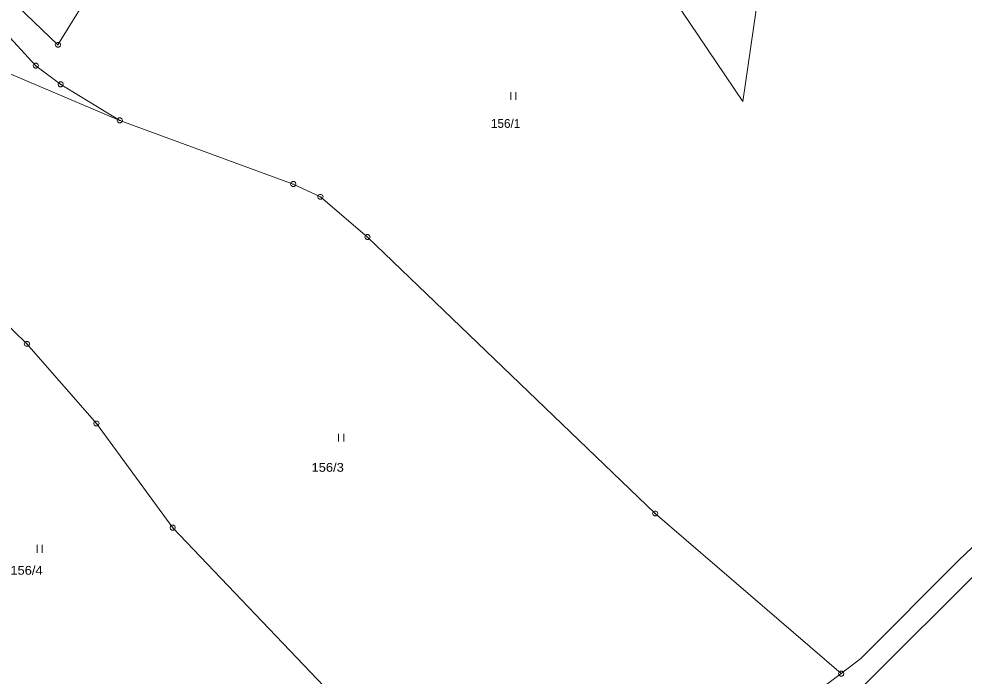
# Model space of a CAD drawing. Extents: x -687390 to -684106, y -954833 to -951648.
# Drawn here: x -686858.8 to -686675.9, y -952746.6 to -952619.4 of the extents above; entities that cross this region are included whole.
import ezdxf

# ---------------------------------------------------------------- set-up
doc = ezdxf.new("R2010")
doc.units = 0
doc.header["$LTSCALE"] = 0.68
for name, color, linetype, lineweight in [('1', 7, 'Continuous', 13), ('3', 7, 'Continuous', 13), ('8', 7, 'Continuous', 13)]:
    doc.layers.add(name, color=color, linetype=linetype, lineweight=lineweight)
doc.layers.add('2', color=7, linetype='Continuous')

msp = doc.modelspace()

# ---------------------------------------------------------------- linework, layer by layer
at = {"layer": '1'}
for p, q in [((-686676.92, -952724.22), (-686653.39, -952701.81)), ((-686695.55, -952748.71), (-686660.3, -952713.48))]:
    msp.add_line(p, q, dxfattribs=at)
for points in [[(-686839.31, -952639.02), (-686850.74, -952632.05), (-686855.56, -952628.43), (-686864.93, -952618.3), (-686863.78, -952612.42), (-686851.28, -952624.39), (-686843.65, -952611.91), (-686852.69, -952606.57), (-686846.38, -952592.59), (-686856.76, -952587.54), (-686854.34, -952579.07)], [(-686742.45, -952600.1), (-686718.74, -952635.39), (-686716.16, -952617.6)], [(-686760.15, -952785.19), (-686787.53, -952759.97), (-686798.41, -952750.05), (-686829.06, -952717.91), (-686843.83, -952697.72), (-686857.28, -952682.32), (-686867.65, -952672.29), (-686876.47, -952664.65), (-686896.54, -952649.2), (-686899.78, -952646.91), (-686884.22, -952620.8)], [(-686865.2, -952628.05), (-686839.31, -952639.02), (-686805.73, -952651.36), (-686800.47, -952653.83), (-686791.36, -952661.63), (-686735.67, -952715.15), (-686699.65, -952746.17)], [(-686699.65, -952746.17), (-686695.9, -952743.26), (-686676.92, -952724.22)], [(-686760.15, -952785.19), (-686748.64, -952784.07), (-686729.34, -952768.34), (-686699.65, -952746.17)]]:
    msp.add_lwpolyline(points, dxfattribs=at)
at = {"layer": '3'}
for p, q in [((-686763.64, -952633.53), (-686763.64, -952635.03)), ((-686762.64, -952635.03), (-686762.64, -952633.53)), ((-686796.97, -952699.7), (-686796.97, -952701.2)), ((-686795.97, -952701.2), (-686795.97, -952699.7)), ((-686855.31, -952721.24), (-686855.31, -952722.74)), ((-686854.31, -952722.74), (-686854.31, -952721.24))]:
    msp.add_line(p, q, dxfattribs=at)
at = {"layer": '8'}
for p, q in [((-686851.4, -952624.39), (-686851.16, -952624.39)), ((-686855.68, -952628.43), (-686855.44, -952628.43)), ((-686850.86, -952632.05), (-686850.62, -952632.05)), ((-686839.43, -952639.02), (-686839.19, -952639.02)), ((-686805.85, -952651.36), (-686805.61, -952651.36)), ((-686800.59, -952653.83), (-686800.35, -952653.83)), ((-686791.48, -952661.63), (-686791.24, -952661.63)), ((-686857.4, -952682.32), (-686857.16, -952682.32)), ((-686843.95, -952697.72), (-686843.71, -952697.72)), ((-686735.79, -952715.15), (-686735.55, -952715.15)), ((-686829.18, -952717.91), (-686828.94, -952717.91)), ((-686699.77, -952746.17), (-686699.53, -952746.17))]:
    msp.add_line(p, q, dxfattribs=at)
for points in [[(-686851.13, -952623.91), (-686850.88, -952624.09), (-686850.78, -952624.38), (-686850.88, -952624.67), (-686851.13, -952624.85), (-686851.44, -952624.85), (-686851.69, -952624.67), (-686851.79, -952624.38), (-686851.69, -952624.09), (-686851.44, -952623.91)], [(-686855.41, -952627.95), (-686855.16, -952628.13), (-686855.06, -952628.42), (-686855.16, -952628.71), (-686855.41, -952628.89), (-686855.72, -952628.89), (-686855.97, -952628.71), (-686856.07, -952628.42), (-686855.97, -952628.13), (-686855.72, -952627.95)], [(-686850.59, -952631.57), (-686850.34, -952631.75), (-686850.24, -952632.04), (-686850.34, -952632.33), (-686850.59, -952632.51), (-686850.9, -952632.51), (-686851.15, -952632.33), (-686851.25, -952632.04), (-686851.15, -952631.75), (-686850.9, -952631.57)], [(-686839.16, -952638.54), (-686838.91, -952638.72), (-686838.81, -952639.01), (-686838.91, -952639.3), (-686839.16, -952639.48), (-686839.47, -952639.48), (-686839.72, -952639.3), (-686839.82, -952639.01), (-686839.72, -952638.72), (-686839.47, -952638.54)], [(-686805.58, -952650.88), (-686805.33, -952651.06), (-686805.23, -952651.35), (-686805.33, -952651.64), (-686805.58, -952651.82), (-686805.89, -952651.82), (-686806.14, -952651.64), (-686806.24, -952651.35), (-686806.14, -952651.06), (-686805.89, -952650.88)], [(-686800.32, -952653.35), (-686800.07, -952653.53), (-686799.97, -952653.82), (-686800.07, -952654.11), (-686800.32, -952654.29), (-686800.63, -952654.29), (-686800.88, -952654.11), (-686800.98, -952653.82), (-686800.88, -952653.53), (-686800.63, -952653.35)], [(-686791.21, -952661.15), (-686790.96, -952661.33), (-686790.86, -952661.62), (-686790.96, -952661.91), (-686791.21, -952662.09), (-686791.52, -952662.09), (-686791.77, -952661.91), (-686791.87, -952661.62), (-686791.77, -952661.33), (-686791.52, -952661.15)], [(-686857.13, -952681.84), (-686856.88, -952682.02), (-686856.78, -952682.31), (-686856.88, -952682.6), (-686857.13, -952682.78), (-686857.44, -952682.78), (-686857.69, -952682.6), (-686857.79, -952682.31), (-686857.69, -952682.02), (-686857.44, -952681.84)], [(-686843.68, -952697.24), (-686843.43, -952697.42), (-686843.33, -952697.71), (-686843.43, -952698), (-686843.68, -952698.18), (-686843.99, -952698.18), (-686844.24, -952698), (-686844.34, -952697.71), (-686844.24, -952697.42), (-686843.99, -952697.24)], [(-686735.52, -952714.67), (-686735.27, -952714.85), (-686735.17, -952715.14), (-686735.27, -952715.43), (-686735.52, -952715.61), (-686735.83, -952715.61), (-686736.08, -952715.43), (-686736.18, -952715.14), (-686736.08, -952714.85), (-686735.83, -952714.67)], [(-686828.91, -952717.43), (-686828.66, -952717.61), (-686828.56, -952717.9), (-686828.66, -952718.19), (-686828.91, -952718.37), (-686829.22, -952718.37), (-686829.47, -952718.19), (-686829.57, -952717.9), (-686829.47, -952717.61), (-686829.22, -952717.43)], [(-686699.5, -952745.69), (-686699.25, -952745.87), (-686699.15, -952746.16), (-686699.25, -952746.45), (-686699.5, -952746.63), (-686699.81, -952746.63), (-686700.06, -952746.45), (-686700.16, -952746.16), (-686700.06, -952745.87), (-686699.81, -952745.69)]]:
    msp.add_lwpolyline(points, close=True, dxfattribs=at)

# ---------------------------------------------------------------- texts
at = {"layer": '2'}
msp.add_text('156/1', height=1.7, dxfattribs=at).set_placement((-686767.475, -952640.47))
at = {"layer": '2', "width": 1.1}
for s, p in [('156/3', (-686802.195, -952707.07)), ('156/4', (-686860.495, -952727.01))]:
    msp.add_text(s, height=1.7, dxfattribs=at).set_placement(p)

doc.saveas('drawing.dxf')
